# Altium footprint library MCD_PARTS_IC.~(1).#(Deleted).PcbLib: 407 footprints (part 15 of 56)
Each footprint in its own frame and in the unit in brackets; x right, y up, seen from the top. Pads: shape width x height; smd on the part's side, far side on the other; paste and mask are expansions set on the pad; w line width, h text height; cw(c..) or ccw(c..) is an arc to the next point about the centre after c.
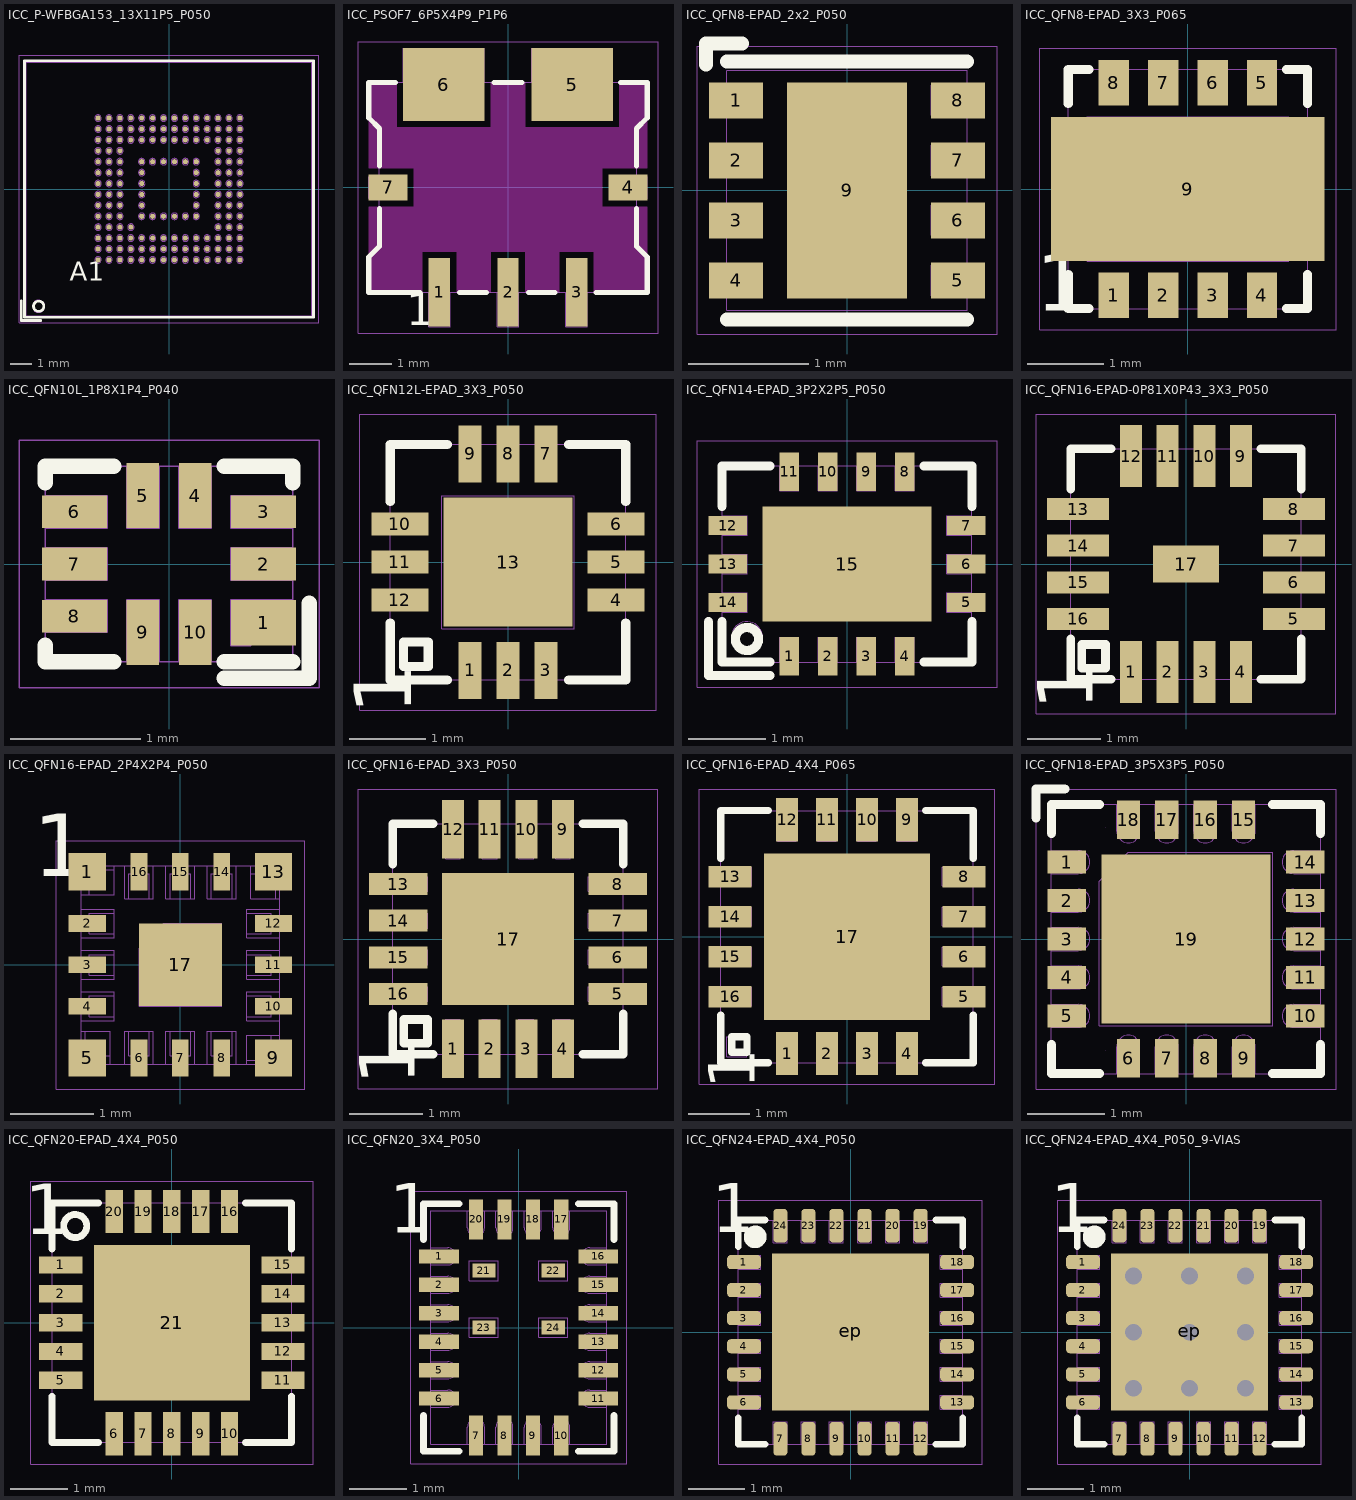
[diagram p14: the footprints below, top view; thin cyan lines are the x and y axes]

## ICC_P-WFBGA153_13X11P5_P050 [mm]
height 1
pads (153):
  round 0.23 smd mask+0.05: A1(-3.25,-3.25) A2(-3.25,-2.75) A3(-3.25,-2.25) A4(-3.25,-1.75) A5(-3.25,-1.25) A6(-3.25,-0.75) A7(-3.25,-0.25) A8(-3.25,0.25) A9(-3.25,0.75) A10(-3.25,1.25) A11(-3.25,1.75) A12(-3.25,2.25) A13(-3.25,2.75) A14(-3.25,3.25) B1(-2.75,-3.25) B2(-2.75,-2.75) B3(-2.75,-2.25) B4(-2.75,-1.75) B5(-2.75,-1.25) B6(-2.75,-0.75) B7(-2.75,-0.25) B8(-2.75,0.25) B9(-2.75,0.75) B10(-2.75,1.25) B11(-2.75,1.75) B12(-2.75,2.25) B13(-2.75,2.75) B14(-2.75,3.25) C1(-2.25,-3.25) C2(-2.25,-2.75) C3(-2.25,-2.25) C4(-2.25,-1.75) C5(-2.25,-1.25) C6(-2.25,-0.75) C7(-2.25,-0.25) C8(-2.25,0.25) C9(-2.25,0.75) C10(-2.25,1.25) C11(-2.25,1.75) C12(-2.25,2.25) C13(-2.25,2.75) C14(-2.25,3.25) D1(-1.75,-3.25) D2(-1.75,-2.75) D3(-1.75,-2.25) D4(-1.75,-1.75) D12(-1.75,2.25) D13(-1.75,2.75) D14(-1.75,3.25) E1(-1.25,-3.25) E2(-1.25,-2.75) E3(-1.25,-2.25) E5(-1.25,-1.25) E6(-1.25,-0.75) E7(-1.25,-0.25) E8(-1.25,0.25) E9(-1.25,0.75) E10(-1.25,1.25) E12(-1.25,2.25) E13(-1.25,2.75) E14(-1.25,3.25) F1(-0.75,-3.25) F2(-0.75,-2.75) F3(-0.75,-2.25) F5(-0.75,-1.25) F10(-0.75,1.25) F12(-0.75,2.25) F13(-0.75,2.75) F14(-0.75,3.25) G1(-0.25,-3.25) G2(-0.25,-2.75) G3(-0.25,-2.25) G5(-0.25,-1.25) G10(-0.25,1.25) G12(-0.25,2.25) G13(-0.25,2.75) G14(-0.25,3.25) H1(0.25,-3.25) H2(0.25,-2.75) H3(0.25,-2.25) H5(0.25,-1.25) H10(0.25,1.25) H12(0.25,2.25) H13(0.25,2.75) H14(0.25,3.25) J1(0.75,-3.25) J2(0.75,-2.75) J3(0.75,-2.25) J5(0.75,-1.25) J10(0.75,1.25) J12(0.75,2.25) J13(0.75,2.75) J14(0.75,3.25) K1(1.25,-3.25) K2(1.25,-2.75) K3(1.25,-2.25) K5(1.25,-1.25) K6(1.25,-0.75) K7(1.25,-0.25) K8(1.25,0.25) K9(1.25,0.75) K10(1.25,1.25) K12(1.25,2.25) K13(1.25,2.75) K14(1.25,3.25) L1(1.75,-3.25) L2(1.75,-2.75) L3(1.75,-2.25) L12(1.75,2.25) L13(1.75,2.75) L14(1.75,3.25) M1(2.25,-3.25) M2(2.25,-2.75) M3(2.25,-2.25) M4(2.25,-1.75) M5(2.25,-1.25) M6(2.25,-0.75) M7(2.25,-0.25) M8(2.25,0.25) M9(2.25,0.75) M10(2.25,1.25) M11(2.25,1.75) M12(2.25,2.25) M13(2.25,2.75) M14(2.25,3.25) N1(2.75,-3.25) N2(2.75,-2.75) N3(2.75,-2.25) N4(2.75,-1.75) N5(2.75,-1.25) N6(2.75,-0.75) N7(2.75,-0.25) N8(2.75,0.25) N9(2.75,0.75) N10(2.75,1.25) N11(2.75,1.75) N12(2.75,2.25) N13(2.75,2.75) N14(2.75,3.25) P1(3.25,-3.25) P2(3.25,-2.75) P3(3.25,-2.25) P4(3.25,-1.75) P5(3.25,-1.25) P6(3.25,-0.75) P7(3.25,-0.25) P8(3.25,0.25) P9(3.25,0.75) P10(3.25,1.25) P11(3.25,1.75) P12(3.25,2.25) P13(3.25,2.75) P14(3.25,3.25)
Top Overlay:
  circle w0.12: c-5.975,-5.375 r0.236
  lines w0.12: -6.775,-5.125 -6.775,-6.025 -5.875,-6.025 ; -6.625,-5.875 6.625,-5.875 6.625,5.875 -6.625,5.875 -6.625,-5.875
  text "A1" at -4.55,-4.5 h1.5
M14-Top Assembly:
  drawing of 158 lines, arcs and shapes, not listed
  text "A1" at -3.5,-3.4 h0.5
  text "'.Designator'" at -2,-0.5 h0.75
M16-Top Courtyard:
  lines w0.01: -6.875,-6.125 6.875,-6.125 6.875,6.125 -6.875,6.125 -6.875,-6.125
3D body "WFBGA-153.STEP": height 0.78, standoff -0.02, extent -6.5,-5.75 6.5,5.75
3D body: height 1, standoff 0, extent -6.555,-5.805 6.555,5.805

## ICC_PSOF7_6P5X4P9_P1P6 [mm] "MCD-04242"
height 1.6
pads (7):
  rect 0.5x1.6 smd mask+0.05: 1(-1.6,-2.45) 2(0,-2.45) 3(1.6,-2.45)
  rect 0.9x0.6 smd mask+0.05: 4(2.8,0) 7(-2.8,0)
  rect 1.9x1.7 smd mask+0.05: 5(1.5,2.4) 6(-1.5,2.4)
Top Overlay:
  lines w0.12: -3,-0.5 -3,-1.375 -3.25,-1.625 -3.25,-2.45 -2.05,-2.45 ; -3,0.5 -3,1.375 -3.25,1.625 -3.25,2.45 -2.625,2.45 ; -1.125,-2.45 -0.5,-2.45 ; -0.325,2.45 0.325,2.45 ; 0.475,-2.45 1.1,-2.45 ; 2.05,-2.45 3.25,-2.45 3.25,-1.625 3,-1.375 3,-0.5 ; 2.625,2.45 3.25,2.45 3.25,1.625 3,1.375 3,0.5
  text "1" at -2.375,-3.475 h1.3
Keep-Out Layer:
  region: -0.4,2.45 0.4,2.45 0.4,1.4 2.6,1.4 2.6,2.45 3.25,2.45 3.25,0.45 2.2,0.45 2.2,-0.45 3.25,-0.45 3.25,-2.45 2,-2.45 2,-1.5 1.2,-1.5 1.2,-2.45 0.4,-2.45 0.4,-1.5 -0.4,-1.5 -0.4,-2.45 -1.2,-2.45 -1.2,-1.5 -2,-1.5 -2,-2.45 -3.25,-2.45 -3.25,-0.45 -2.2,-0.45 -2.2,0.45 -3.25,0.45 -3.25,2.45 -2.6,2.45 -2.6,1.4 -0.4,1.4
M14-Top Assembly:
  lines w0.01: -2.45,2.45 -2.45,3.25 -0.55,3.25 -0.55,2.45 ; -1.85,-2.45 -1.85,-3.25 -1.35,-3.25 -1.35,-2.45 ; -0.25,-2.45 -0.25,-3.25 0.25,-3.25 0.25,-2.45 ; 0.55,2.45 0.55,3.25 2.45,3.25 2.45,2.45 ; 1.35,-2.45 1.35,-3.25 1.85,-3.25 1.85,-2.45 ; -3,-0.25 -3,-1.375 -3.25,-1.625 -3.25,-2.45 3.25,-2.45 3.25,-1.625 3,-1.375 3,-0.25 ; -3,-0.25 -3.25,-0.25 -3.25,0.25 -3,0.25 ; -3,-0.25 -3,0.25 ; -3,0.25 -3,1.375 -3.25,1.625 -3.25,2.45 3.25,2.45 3.25,1.625 3,1.375 3,0.25 ; 3,-0.25 3.25,-0.25 3.25,0.25 3,0.25 ; 3,-0.25 3,0.25
  text "1" at -1.8,-3.25 h1.3
  text "'.Designator'" at -2,-0.5 h0.75
M16-Top Courtyard:
  lines w0.01: -3.5,-3.4 3.5,-3.4 3.5,3.4 -3.5,3.4 -3.5,-3.4
3D body: height 0.35, standoff 0, extent 1.35,-3.25 1.85,-2.45
3D body: height 0.35, standoff 0, extent -0.25,-3.25 0.25,-2.45
3D body: height 0.35, standoff 0, extent 3,-0.25 3.25,0.25
3D body: height 0.35, standoff 0, extent 0.55,2.45 2.45,3.25
3D body: height 0.35, standoff 0, extent -2.45,2.45 -0.55,3.25
3D body: height 0.35, standoff 0, extent -1.85,-3.25 -1.35,-2.45
3D body: height 0.35, standoff 0, extent -3.25,-0.25 -3,0.25
3D body: height 1.6, standoff 0, extent -3,-2.45 3,2.45

## ICC_QFN8-EPAD_2x2_P050 [mm] "MCD-03561"
height 1
pads (9):
  rect 0.45x0.3 smd mask+0.05: 1(-0.925,0.75) 2(-0.925,0.25) 3(-0.925,-0.25) 4(-0.925,-0.75) 5(0.925,-0.75) 6(0.925,-0.25) 7(0.925,0.25) 8(0.925,0.75)
  rect 1x1.8 smd mask+0.05: 9(0,0)
Top Overlay:
  lines w0.12: -1.175,1.05 -1.175,1.225 -0.875,1.225 ; -1,-1.075 1,-1.075 ; -1,1.075 1,1.075
M14-Top Assembly:
  lines w0.01: -1,-0.875 -0.7,-0.875 -0.7,-0.625 -1,-0.625 ; -1,-0.375 -0.7,-0.375 -0.7,-0.125 -1,-0.125 ; -1,0.125 -0.7,0.125 -0.7,0.375 -1,0.375 ; -1,0.625 -0.7,0.625 -0.7,0.875 -1,0.875 ; 1,-0.875 0.7,-0.875 0.7,-0.625 1,-0.625 ; 1,-0.375 0.7,-0.375 0.7,-0.125 1,-0.125 ; 1,0.125 0.7,0.125 0.7,0.375 1,0.375 ; 1,0.625 0.7,0.625 0.7,0.875 1,0.875 ; -1,-1 ccw(c-1,-1) -1,-1 1,-1 1,1 -1,1 ccw(c-1,1) -1,1 -1,-1 ; -0.45,-0.85 0.45,-0.85 0.45,0.85 -0.45,0.85 -0.45,-0.85
  text "'.Designator'" at -1.813,-0.17 h0.75
  text "1" at -0.891,0.638 h0.35
  text "4" at -0.927,-0.862 h0.35
  text "5" at 0.776,-0.858 h0.35
  text "8" at 0.776,0.64 h0.35
  text "9" at -0.073,-0.11 h0.35
M16-Top Courtyard:
  lines w0.01: -1.25,-1.2 1.25,-1.2 1.25,1.2 -1.25,1.2 -1.25,-1.2
3D body "QFN8.STEP": height 0.95, standoff 0, extent -1.05,-1 1.05,1

## ICC_QFN8-EPAD_3X3_P065 [mm]
height 1
pads (9):
  rect 0.4x0.6 smd paste+0 mask+0.05: 1(-0.975,-1.4) 2(-0.325,-1.4) 3(0.325,-1.4) 4(0.975,-1.4) 5(0.975,1.4) 6(0.325,1.4) 7(-0.325,1.4) 8(-0.975,1.4)
  rect 3.6x1.9 smd paste+0 mask+0: 9(0,0)
Top Overlay:
  lines w0.12: -1.575,-1.125 -1.575,-1.575 -1.3,-1.575 ; -1.575,1.125 -1.575,1.575 -1.3,1.575 ; 1.3,-1.575 1.575,-1.575 1.575,-1.125 ; 1.3,1.575 1.575,1.575 1.575,1.125
  text "1" at -2,-1.85 h1.3
M14-Top Assembly:
  lines w0.01: -1.15,-1.575 -1.15,-1.2 -0.8,-1.2 -0.8,-1.575 ; -1.15,1.575 -1.15,1.2 -0.8,1.2 -0.8,1.575 ; -0.5,-1.575 -0.5,-1.2 -0.15,-1.2 -0.15,-1.575 ; -0.5,1.575 -0.5,1.2 -0.15,1.2 -0.15,1.575 ; 0.15,-1.575 0.15,-1.2 0.5,-1.2 0.5,-1.575 ; 0.15,1.575 0.15,1.2 0.5,1.2 0.5,1.575 ; 0.8,-1.575 0.8,-1.2 1.15,-1.2 1.15,-1.575 ; 0.8,1.575 0.8,1.2 1.15,1.2 1.15,1.575 ; -1.575,-1.575 1.575,-1.575 1.575,1.575 -1.575,1.575 -1.575,-1.575 ; -1.575,-0.45 -1.525,-0.45 -1.325,-0.45 -1.325,-0.95 1.325,-0.95 1.325,-0.45 1.575,-0.45 1.575,-0.25 1.325,-0.25 1.325,0.25 1.575,0.25 1.575,0.45 1.325,0.45 1.325,0.95 -1.325,0.95 -1.325,0.45 -1.575,0.45 -1.575,0.25 -1.325,0.25 -1.325,-0.25 -1.575,-0.25 -1.575,-0.45
  text "1" at -1.075,-1.55 h0.7
  text "4" at 0.8,-1.55 h0.7
  text "5" at 0.825,1.1 h0.7
  text "8" at -1.125,1.1 h0.7
  text "'.Designator'" at -2,-0.5 h0.75
M16-Top Courtyard:
  lines w0.01: -1.95,-1.85 -1.95,1.85 1.95,1.85 1.95,-1.85 -1.95,-1.85
3D body: height 1, standoff 0, extent -1.58,-1.58 1.58,1.58
3D body "QFN8-EPAD-3X3-P065.STEP": height 0.9, standoff 0, extent -1.5,-1.501 1.5,1.501

## ICC_QFN10L_1P8X1P4_P040 [mm] "SOLDER MASK REGISTRATION 38UM"
height 0.55
pads (10):
  rect 0.5x0.35 smd mask+0.038: 1(0.725,-0.45)
  rect 0.5x0.25 smd mask+0.038: 2(0.725,0) 3(0.725,0.4) 6(-0.725,0.4) 7(-0.725,0) 8(-0.725,-0.4)
  rect 0.25x0.5 smd mask+0.038: 4(0.2,0.525) 5(-0.2,0.525) 9(-0.2,-0.525) 10(0.2,-0.525)
Top Overlay:
  lines w0.12: -0.95,-0.625 -0.95,-0.75 -0.425,-0.75 ; -0.95,0.625 -0.95,0.75 -0.425,0.75 ; 0.425,-0.875 1.075,-0.875 1.075,-0.3 ; 0.425,-0.75 0.95,-0.75 ; 0.425,0.75 0.95,0.75 0.95,0.625
M14-Top Assembly:
  lines w0.01: -0.95,-0.525 -0.475,-0.525 -0.475,-0.275 -0.95,-0.275 ; -0.95,-0.125 -0.475,-0.125 -0.475,0.125 -0.95,0.125 ; -0.95,0.275 -0.475,0.275 -0.475,0.525 -0.95,0.525 ; -0.325,-0.75 -0.325,-0.275 -0.075,-0.275 -0.075,-0.75 ; -0.325,0.75 -0.325,0.275 -0.075,0.275 -0.075,0.75 ; 0.075,-0.75 0.075,-0.275 0.325,-0.275 0.325,-0.75 ; 0.075,0.75 0.075,0.275 0.325,0.275 0.325,0.75 ; 0.95,-0.525 0.625,-0.525 0.625,-0.625 0.475,-0.625 0.475,-0.525 0.475,-0.275 0.95,-0.275 ; 0.95,-0.125 0.475,-0.125 0.475,0.125 0.95,0.125 ; 0.95,0.275 0.475,0.275 0.475,0.525 0.95,0.525 ; -0.95,-0.75 -0.95,0.75 0.95,0.75 0.95,-0.75 -0.95,-0.75
  text "10" at 0,-0.7 h0.5
  text "9" at -0.3,-0.7 h0.5
  text "8" at -0.9,-0.3 h0.5
  text "7" at -0.9,0.1 h0.5
  text "6" at -0.9,0.5 h0.5
  text "5" at -0.3,0.4 h0.5
  text "4" at 0.1,0.4 h0.5
  text "3" at 0.9,0.3 h0.5
  text "2" at 0.9,-0.1 h0.5
  text "1" at 0.9,-0.475 h0.5
  text "'.Designator'" at -2,-0.5 h0.75
M16-Top Courtyard:
  lines w0.01: -1.15,-0.95 -1.15,0.95 1.15,0.95 1.15,-0.95 -1.15,-0.95
3D body: height 0.55, standoff 0, extent -0.95,-0.75 0.95,0.75
3D body: height 0.56, standoff 0.55, extent 0.621,-0.68 0.88,-0.42

## ICC_QFN12L-EPAD_3X3_P050 [mm] "MCD-01809"
height 0.8
pads (13):
  rect 0.3x0.75 smd mask+0.05: 1(-0.5,-1.425) 2(0,-1.425) 3(0.5,-1.425) 7(0.5,1.425) 8(0,1.425) 9(-0.5,1.425)
  rect 0.75x0.3 smd mask+0.05: 4(1.425,-0.5) 5(1.425,0) 6(1.425,0.5) 10(-1.425,0.5) 11(-1.425,0) 12(-1.425,-0.5)
  rect 1.7x1.7 smd mask+0.05: 13(0,0)
Top Overlay:
  lines w0.12: -1.55,-0.8 -1.55,-1.55 -0.8,-1.55 ; -1.55,0.8 -1.55,1.55 -0.8,1.55 ; 0.8,-1.55 1.55,-1.55 1.55,-0.8 ; 0.8,1.55 1.55,1.55 1.55,0.8 ; -1.375,-1.375 -1.05,-1.375 -1.05,-1.05 -1.375,-1.05 -1.375,-1.375
  text "1" at -1.025,-2 h1.3
M14-Top Assembly:
  lines w0.01: -1.55,-0.6 -1.15,-0.6 -1.15,-0.4 -1.55,-0.4 ; -1.55,-0.1 -1.15,-0.1 -1.15,0.1 -1.55,0.1 ; -1.55,0.4 -1.15,0.4 -1.15,0.6 -1.55,0.6 ; -0.6,-1.55 -0.6,-1.15 -0.4,-1.15 -0.4,-1.55 ; -0.6,1.55 -0.6,1.15 -0.4,1.15 -0.4,1.55 ; -0.1,-1.55 -0.1,-1.15 0.1,-1.15 0.1,-1.55 ; -0.1,1.55 -0.1,1.15 0.1,1.15 0.1,1.55 ; 0.4,-1.55 0.4,-1.15 0.6,-1.15 0.6,-1.55 ; 0.4,1.55 0.4,1.15 0.6,1.15 0.6,1.55 ; 1.55,-0.6 1.15,-0.6 1.15,-0.4 1.55,-0.4 ; 1.55,-0.1 1.15,-0.1 1.15,0.1 1.55,0.1 ; 1.55,0.4 1.15,0.4 1.15,0.6 1.55,0.6 ; -1.55,-1.55 -1.55,1.55 1.55,1.55 1.55,-1.55 -1.55,-1.55 ; -1.375,-1.375 -1.05,-1.375 -1.05,-1.05 -1.375,-1.05 -1.375,-1.375 ; -0.875,-0.875 0.875,-0.875 0.875,0.875 -0.875,0.875 -0.875,-0.875
  text "'.Designator'" at -2,-0.5 h0.75
  text "13" at -0.15,-0.125 h0.4
  text "9" at -0.575,1.225 h0.4
  text "7" at 0.425,1.2 h0.4
  text "6" at 1.275,0.375 h0.4
  text "4" at 1.25,-0.65 h0.4
  text "3" at 0.425,-1.475 h0.4
  text "1" at -0.575,-1.475 h0.4
  text "10" at -1.525,0.4 h0.4
  text "12" at -1.5,-0.625 h0.4
M16-Top Courtyard:
  lines w0.01: -1.95,-1.95 -1.95,1.95 1.95,1.95 1.95,-1.95 -1.95,-1.95
3D body "User Library-QFN12_3x3x0_8.STEP": height 0.78, standoff -0.02, extent -1.51,-1.51 1.51,1.51
3D body: height 0.8, standoff 0, extent -1.55,-1.55 1.55,1.55

## ICC_QFN14-EPAD_3P2X2P5_P050 [mm] "MCD-02349"
height 0.9
pads (15):
  rect 0.25x0.5 smd mask+0.05: 1(-0.75,-1.2) 2(-0.25,-1.2) 3(0.25,-1.2) 4(0.75,-1.2) 8(0.75,1.2) 9(0.25,1.2) 10(-0.25,1.2) 11(-0.75,1.2)
  rect 0.5x0.25 smd mask+0.05: 5(1.55,-0.5) 6(1.55,0) 7(1.55,0.5) 12(-1.55,0.5) 13(-1.55,0) 14(-1.55,-0.5)
  rect 2.2x1.5 smd mask+0.05: 15(0,0)
Top Overlay:
  circle w0.12: c-1.3,-0.975 r0.15
  lines w0.12: -1.8,-0.75 -1.8,-1.45 -1,-1.45 ; -1.625,-0.75 -1.625,-1.275 -1,-1.275 ; -1.625,0.75 -1.625,1.275 -1,1.275 ; 1,-1.275 1.625,-1.275 1.625,-0.75 ; 1,1.275 1.625,1.275 1.625,0.75
M14-Top Assembly:
  circle w0.01: c-1.3,-0.95 r0.2
  lines w0.01: -1.625,-0.625 -1.3,-0.625 -1.3,-0.375 -1.625,-0.375 ; -1.625,-0.125 -1.3,-0.125 -1.3,0.125 -1.625,0.125 ; -1.625,0.375 -1.3,0.375 -1.3,0.625 -1.625,0.625 ; -0.875,-1.275 -0.875,-0.95 -0.625,-0.95 -0.625,-1.275 ; -0.875,1.275 -0.875,0.95 -0.625,0.95 -0.625,1.275 ; -0.375,-1.275 -0.375,-0.95 -0.125,-0.95 -0.125,-1.275 ; -0.375,1.275 -0.375,0.95 -0.125,0.95 -0.125,1.275 ; 0.125,-1.275 0.125,-0.95 0.375,-0.95 0.375,-1.275 ; 0.125,1.275 0.125,0.95 0.375,0.95 0.375,1.275 ; 0.625,-1.275 0.625,-0.95 0.875,-0.95 0.875,-1.275 ; 0.625,1.275 0.625,0.95 0.875,0.95 0.875,1.275 ; 1.625,-0.625 1.3,-0.625 1.3,-0.375 1.625,-0.375 ; 1.625,-0.125 1.3,-0.125 1.3,0.125 1.625,0.125 ; 1.625,0.375 1.3,0.375 1.3,0.625 1.625,0.625 ; -1.625,-1.275 -1.625,1.275 1.625,1.275 1.625,-1.275 -1.625,-1.275 ; -1.05,-0.45 -1.05,0.7 1.05,0.7 1.05,-0.7 -0.8,-0.7 -1.05,-0.45
  text "15" at -0.175,-0.125 h0.4
  text "14" at -1.6,-0.325 h0.4
  text "12" at -1.6,0.675 h0.4
  text "11" at -0.9,1 h0.4
  text "8" at 0.675,1 h0.4
  text "7" at 1.6,0.425 h0.4
  text "5" at 1.6,-0.575 h0.4
  text "4" at 0.65,-1.25 h0.4
  text "'.Designator'" at -2,-0.025 h0.75
  text "1" at -0.8,-1.25 h0.4
M16-Top Courtyard:
  lines w0.01: -1.95,-1.6 1.95,-1.6 1.95,1.6 -1.95,1.6 -1.95,-1.6
3D body: height 0.86, standoff 0.85, extent -1.499,-1.15 -1.101,-0.75
3D body: height 0.85, standoff 0.05, extent -1.625,-1.275 1.625,1.275
3D body: height 0.05, standoff 0, extent -1.625,0.375 -1.3,0.625
3D body: height 0.05, standoff 0, extent -1.625,-0.125 -1.3,0.125
3D body: height 0.05, standoff 0, extent -1.625,-0.625 -1.3,-0.375
3D body: height 0.05, standoff 0, extent -0.875,-1.275 -0.625,-0.95
3D body: height 0.05, standoff 0, extent -0.375,-1.275 -0.125,-0.95
3D body: height 0.05, standoff 0, extent 0.125,-1.275 0.375,-0.95
3D body: height 0.05, standoff 0, extent 0.625,-1.275 0.875,-0.95
3D body: height 0.05, standoff 0, extent 1.3,-0.625 1.625,-0.375
3D body: height 0.05, standoff 0, extent 1.3,-0.125 1.625,0.125
3D body: height 0.05, standoff 0, extent 1.3,0.375 1.625,0.625
3D body: height 0.05, standoff 0, extent 0.625,0.95 0.875,1.275
3D body: height 0.05, standoff 0, extent 0.125,0.95 0.375,1.275
3D body: height 0.05, standoff 0, extent -0.375,0.95 -0.125,1.275
3D body: height 0.05, standoff 0, extent -0.875,0.95 -0.625,1.275
3D body: height 0.05, standoff 0, extent -1.05,-0.7 1.05,0.7

## ICC_QFN16-EPAD-0P81X0P43_3X3_P050 [mm] "MCD-02527"
height 0.8
pads (17):
  rect 0.3x0.85 smd mask+0.05: 1(-0.75,-1.475) 2(-0.25,-1.475) 3(0.25,-1.475) 4(0.75,-1.475) 9(0.75,1.475) 10(0.25,1.475) 11(-0.25,1.475) 12(-0.75,1.475)
  rect 0.85x0.3 smd mask+0.05: 5(1.475,-0.75) 6(1.475,-0.25) 7(1.475,0.25) 8(1.475,0.75) 13(-1.475,0.75) 14(-1.475,0.25) 15(-1.475,-0.25) 16(-1.475,-0.75)
  rect 0.9x0.5 smd mask+0.05: 17(0,0)
Top Overlay:
  lines w0.12: -1.575,-1.025 -1.575,-1.575 -1.55,-1.575 -1.025,-1.575 ; -1.575,1.025 -1.575,1.575 -1.025,1.575 ; 1.025,-1.575 1.575,-1.575 1.575,-1.025 ; 1.025,1.575 1.575,1.575 1.575,1.025 ; -1.425,-1.425 -1.1,-1.425 -1.1,-1.1 -1.425,-1.1 -1.425,-1.425
  text "1" at -1.025,-2 h1.3
M14-Top Assembly:
  lines w0.01: -1.575,-0.85 -1.1,-0.85 -1.1,-0.65 -1.575,-0.65 ; -1.575,-0.35 -1.1,-0.35 -1.1,-0.15 -1.575,-0.15 ; -1.575,0.15 -1.1,0.15 -1.1,0.35 -1.575,0.35 ; -1.575,0.65 -1.1,0.65 -1.1,0.85 -1.575,0.85 ; -0.85,-1.575 -0.85,-1.1 -0.65,-1.1 -0.65,-1.575 ; -0.85,1.575 -0.85,1.1 -0.65,1.1 -0.65,1.575 ; -0.35,-1.575 -0.35,-1.1 -0.15,-1.1 -0.15,-1.575 ; -0.35,1.575 -0.35,1.1 -0.15,1.1 -0.15,1.575 ; 0.15,-1.575 0.15,-1.1 0.35,-1.1 0.35,-1.575 ; 0.15,1.575 0.15,1.1 0.35,1.1 0.35,1.575 ; 0.65,-1.575 0.65,-1.1 0.85,-1.1 0.85,-1.575 ; 0.65,1.575 0.65,1.1 0.85,1.1 0.85,1.575 ; 1.575,-0.85 1.1,-0.85 1.1,-0.65 1.575,-0.65 ; 1.575,-0.35 1.1,-0.35 1.1,-0.15 1.575,-0.15 ; 1.575,0.15 1.1,0.15 1.1,0.35 1.575,0.35 ; 1.575,0.65 1.1,0.65 1.1,0.85 1.575,0.85 ; -1.575,-1.575 -1.575,1.575 1.575,1.575 1.575,-1.575 -1.575,-1.575 ; -1.425,-1.425 -1.1,-1.425 -1.1,-1.1 -1.425,-1.1 -1.425,-1.425 ; -0.405,-0.215 0.405,-0.215 0.405,0.215 -0.405,0.215 -0.405,-0.215
  text "'.Designator'" at -2,-0.5 h0.75
  text "17" at -0.15,-0.125 h0.4
  text "16" at -1.507,-0.874 h0.4
  text "13" at -1.503,0.628 h0.4
  text "12" at -0.925,1.175 h0.4
  text "9" at 0.671,1.177 h0.4
  text "8" at 1.25,0.625 h0.4
  text "5" at 1.25,-0.875 h0.4
  text "4" at 0.66,-1.449 h0.4
  text "1" at -0.805,-1.449 h0.4
M16-Top Courtyard:
  lines w0.01: -2.05,-2.05 -2.05,2.05 2.05,2.05 2.05,-2.05 -2.05,-2.05
3D body: height 0.8, standoff 0, extent -1.575,-1.575 1.575,1.575
3D body "QFN16-EPAD_3X3_P050.STEP": height 0.9, standoff 0, extent -1.501,-1.501 1.501,1.501

## ICC_QFN16-EPAD_2P4X2P4_P050 [mm] "MCD-03832"
height 0.8
pads (17):
  rect 0.45x0.45 smd mask+0.05: 1(-1.125,1.125) 5(-1.125,-1.125) 9(1.125,-1.125) 13(1.125,1.125)
  rect 0.45x0.2 smd mask+0.05: 2(-1.125,0.5) 3(-1.125,0) 4(-1.125,-0.5) 10(1.125,-0.5) 11(1.125,0) 12(1.125,0.5)
  rect 0.2x0.45 smd mask+0.05: 6(-0.5,-1.125) 7(0,-1.125) 8(0.5,-1.125) 14(0.5,1.125) 15(0,1.125) 16(-0.5,1.125)
  rect 1x1 smd mask+0.05: 17(0,0)
Top Overlay:
  text "1" at -1.775,0.825 h1.3
M14-Top Assembly:
  lines w0.01: -1.15,-0.8 -1.15,-1.1 -0.85,-1.1 ; -1.1,0.85 -1.1,1.15 -0.8,1.15 ; -0.8,-0.625 -1.1,-0.625 -1.1,-0.375 -0.8,-0.375 ; -0.8,-0.125 -1.1,-0.125 -1.1,0.125 -0.8,0.125 ; -0.8,0.375 -1.1,0.375 -1.1,0.625 -0.8,0.625 ; -0.625,-0.8 -0.625,-1.1 -0.375,-1.1 -0.375,-0.8 ; -0.625,0.8 -0.625,1.1 -0.375,1.1 -0.375,0.8 ; -0.125,-0.8 -0.125,-1.1 0.125,-1.1 0.125,-0.8 ; -0.125,0.8 -0.125,1.1 0.125,1.1 0.125,0.8 ; 0.375,-0.8 0.375,-1.1 0.625,-1.1 0.625,-0.8 ; 0.375,0.8 0.375,1.1 0.625,1.1 0.625,0.8 ; 0.8,-1.15 1.1,-1.15 1.1,-0.85 ; 0.8,-0.625 1.1,-0.625 1.1,-0.375 0.8,-0.375 ; 0.8,-0.125 1.1,-0.125 1.1,0.125 0.8,0.125 ; 0.8,0.375 1.1,0.375 1.1,0.625 0.8,0.625 ; 0.85,1.1 1.15,1.1 1.15,0.8 ; -1.2,-1.2 1.2,-1.2 ; -1.2,-1.2 -1.2,1.2 ; -1.2,-1.2 -1.2,-0.8 -0.85,-0.8 -0.85,-1.2 -1.2,-1.2 ; -1.2,1.2 -1.2,0.85 -0.8,0.85 -0.8,1.2 -1.2,1.2 ; -1.2,1.2 1.2,1.2 ; 1.2,-1.2 1.2,-0.85 0.8,-0.85 0.8,-1.2 1.2,-1.2 ; 1.2,-1.2 1.2,1.2 ; 1.2,1.2 0.85,1.2 0.85,0.8 1.2,0.8 1.2,1.2 ; -1.2,-0.675 -0.8,-0.675 -0.8,-0.325 -1.2,-0.325 -1.2,-0.675 ; -1.2,-0.175 -0.8,-0.175 -0.8,0.175 -1.2,0.175 -1.2,-0.175 ; -1.2,0.325 -0.8,0.325 -0.8,0.675 -1.2,0.675 -1.2,0.325 ; -0.675,-1.2 -0.325,-1.2 -0.325,-0.8 -0.675,-0.8 -0.675,-1.2 ; -0.675,0.8 -0.675,1.2 -0.325,1.2 -0.325,0.8 -0.675,0.8 ; -0.5,-0.5 -0.5,0.2 -0.2,0.5 0.5,0.5 0.5,-0.5 -0.5,-0.5 ; -0.175,-1.2 0.175,-1.2 0.175,-0.8 -0.175,-0.8 -0.175,-1.2 ; -0.175,0.8 -0.175,1.2 0.175,1.2 0.175,0.8 -0.175,0.8 ; 0.325,-1.2 0.675,-1.2 0.675,-0.8 0.325,-0.8 0.325,-1.2 ; 0.325,0.8 0.325,1.2 0.675,1.2 0.675,0.8 0.325,0.8 ; 0.8,-0.675 0.8,-0.325 1.2,-0.325 1.2,-0.675 0.8,-0.675 ; 0.8,-0.175 0.8,0.175 1.2,0.175 1.2,-0.175 0.8,-0.175 ; 0.8,0.325 0.8,0.675 1.2,0.675 1.2,0.325 0.8,0.325
  text "'.Designator'" at -2,-0.5 h0.75
  text "17" at -0.15,-0.125 h0.4
  text "16" at -0.675,0.825 h0.4
  text "13" at 0.825,0.825 h0.4
  text "9" at 0.875,-1.125 h0.4
  text "5" at -1.075,-1.075 h0.4
  text "1" at -1.025,0.875 h0.4
M16-Top Courtyard:
  lines w0.01: -1.5,-1.5 -1.5,1.5 1.5,1.5 1.5,-1.5 -1.5,-1.5
3D body: height 0.81, standoff 0.8, extent -0.95,0.688 -0.65,0.988
3D body: height 0.8, standoff 0, extent -1.2,-1.2 1.2,1.2

## ICC_QFN16-EPAD_3X3_P050 [mm]
height 1
pads (17):
  rect 0.3x0.8 smd mask+0.05: 1(-0.75,-1.5) 2(-0.25,-1.5) 3(0.25,-1.5) 4(0.75,-1.5) 9(0.75,1.5) 10(0.25,1.5) 11(-0.25,1.5) 12(-0.75,1.5)
  rect 0.8x0.3 smd mask+0.05: 5(1.5,-0.75) 6(1.5,-0.25) 7(1.5,0.25) 8(1.5,0.75) 13(-1.5,0.75) 14(-1.5,0.25) 15(-1.5,-0.25) 16(-1.5,-0.75)
  rect 1.8x1.8 smd mask+0.05: 17(0,0)
Top Overlay:
  lines w0.12: -1.575,-1.025 -1.575,-1.575 -1.55,-1.575 -1.025,-1.575 ; -1.575,1.025 -1.575,1.575 -1.025,1.575 ; 1.025,-1.575 1.575,-1.575 1.575,-1.025 ; 1.025,1.575 1.575,1.575 1.575,1.025 ; -1.425,-1.425 -1.1,-1.425 -1.1,-1.1 -1.425,-1.1 -1.425,-1.425
  text "1" at -1.025,-2 h1.3
M14-Top Assembly:
  lines w0.01: -1.575,-0.85 -1.1,-0.85 -1.1,-0.65 -1.575,-0.65 ; -1.575,-0.35 -1.1,-0.35 -1.1,-0.15 -1.575,-0.15 ; -1.575,0.15 -1.1,0.15 -1.1,0.35 -1.575,0.35 ; -1.575,0.65 -1.1,0.65 -1.1,0.85 -1.575,0.85 ; -0.85,-1.575 -0.85,-1.1 -0.65,-1.1 -0.65,-1.575 ; -0.85,1.575 -0.85,1.1 -0.65,1.1 -0.65,1.575 ; -0.35,-1.575 -0.35,-1.1 -0.15,-1.1 -0.15,-1.575 ; -0.35,1.575 -0.35,1.1 -0.15,1.1 -0.15,1.575 ; 0.15,-1.575 0.15,-1.1 0.35,-1.1 0.35,-1.575 ; 0.15,1.575 0.15,1.1 0.35,1.1 0.35,1.575 ; 0.65,-1.575 0.65,-1.1 0.85,-1.1 0.85,-1.575 ; 0.65,1.575 0.65,1.1 0.85,1.1 0.85,1.575 ; 1.575,-0.85 1.1,-0.85 1.1,-0.65 1.575,-0.65 ; 1.575,-0.35 1.1,-0.35 1.1,-0.15 1.575,-0.15 ; 1.575,0.15 1.1,0.15 1.1,0.35 1.575,0.35 ; 1.575,0.65 1.1,0.65 1.1,0.85 1.575,0.85 ; -1.575,-1.575 -1.575,1.575 1.575,1.575 1.575,-1.575 -1.575,-1.575 ; -1.425,-1.425 -1.1,-1.425 -1.1,-1.1 -1.425,-1.1 -1.425,-1.425 ; -0.85,-0.85 0.85,-0.85 0.85,0.85 -0.85,0.85 -0.85,-0.85
  text "'.Designator'" at -2,0 h0.75
  text "17" at -0.15,-0.125 h0.4
  text "16" at -1.507,-0.874 h0.4
  text "13" at -1.503,0.628 h0.4
  text "12" at -0.925,1.175 h0.4
  text "9" at 0.671,1.177 h0.4
  text "8" at 1.25,0.625 h0.4
  text "5" at 1.25,-0.875 h0.4
  text "4" at 0.66,-1.449 h0.4
  text "1" at -0.805,-1.449 h0.4
M16-Top Courtyard:
  lines w0.01: -2.05,-2.05 -2.05,2.05 2.05,2.05 2.05,-2.05 -2.05,-2.05
3D body: height 1, standoff 0, extent -1.575,-1.575 1.575,1.575
3D body "QFN16-EPAD_3X3_P050.STEP": height 0.9, standoff 0, extent -1.501,-1.501 1.501,1.501

## ICC_QFN16-EPAD_4X4_P065 [mm]
height 1
pads (17):
  rect 0.35x0.7 smd mask+0.05: 1(-0.975,-1.9) 2(-0.325,-1.9) 3(0.325,-1.9) 4(0.975,-1.9) 9(0.975,1.9) 10(0.325,1.9) 11(-0.325,1.9) 12(-0.975,1.9)
  rect 0.7x0.35 smd mask+0.05: 5(1.9,-0.975) 6(1.9,-0.325) 7(1.9,0.325) 8(1.9,0.975) 13(-1.9,0.975) 14(-1.9,0.325) 15(-1.9,-0.325) 16(-1.9,-0.975)
  rect 2.7x2.7 smd mask+0.05: 17(0,0)
Top Overlay:
  lines w0.12: -2.05,-1.275 -2.05,-2.05 -1.275,-2.05 ; -2.05,1.275 -2.05,2.05 -1.275,2.05 ; 1.275,-2.05 2.05,-2.05 2.05,-1.275 ; 1.275,2.05 2.05,2.05 2.05,1.275 ; -1.875,-1.875 -1.875,-1.625 -1.625,-1.625 -1.625,-1.875 -1.875,-1.875
  text "1" at -1.25,-2.475 h1.3
M14-Top Assembly:
  lines w0.01: -2.05,-1.125 -1.55,-1.125 -1.55,-0.825 -2.05,-0.825 ; -2.05,-0.475 -1.55,-0.475 -1.55,-0.175 -2.05,-0.175 ; -2.05,0.175 -1.55,0.175 -1.55,0.475 -2.05,0.475 ; -2.05,0.825 -1.55,0.825 -1.55,1.125 -2.05,1.125 ; -1.125,-2.05 -1.125,-1.55 -0.825,-1.55 -0.825,-2.05 ; -1.125,2.05 -1.125,1.55 -0.825,1.55 -0.825,2.05 ; -0.475,-2.05 -0.475,-1.55 -0.175,-1.55 -0.175,-2.05 ; -0.475,2.05 -0.475,1.55 -0.175,1.55 -0.175,2.05 ; 0.175,-2.05 0.175,-1.55 0.475,-1.55 0.475,-2.05 ; 0.175,2.05 0.175,1.55 0.475,1.55 0.475,2.05 ; 0.825,-2.05 0.825,-1.55 1.125,-1.55 1.125,-2.05 ; 0.825,2.05 0.825,1.55 1.125,1.55 1.125,2.05 ; 2.05,-1.125 1.55,-1.125 1.55,-0.825 2.05,-0.825 ; 2.05,-0.475 1.55,-0.475 1.55,-0.175 2.05,-0.175 ; 2.05,0.175 1.55,0.175 1.55,0.475 2.05,0.475 ; 2.05,0.825 1.55,0.825 1.55,1.125 2.05,1.125 ; -2.05,-2.05 -2.05,2.05 2.05,2.05 2.05,-2.05 -2.05,-2.05 ; -1.95,-1.95 -1.625,-1.95 -1.625,-1.625 -1.95,-1.625 -1.95,-1.95
  text "16" at -1.975,-1.1 h0.4
  text "13" at -1.975,0.85 h0.4
  text "12" at -1.15,1.675 h0.4
  text "9" at 0.9,1.675 h0.4
  text "8" at 1.725,0.85 h0.4
  text "5" at 1.725,-1.1 h0.4
  text "4" at 0.875,-1.95 h0.4
  text "1" at -1.025,-1.95 h0.4
  text "'.Designator'" at -2,-0.5 h0.75
M16-Top Courtyard:
  lines w0.01: -2.4,-2.4 -2.4,2.4 2.4,2.4 2.4,-2.4 -2.4,-2.4
3D body "QFN16-EPAD_4X4_P065.STEP": height 0.85, standoff 0, extent -2.085,-2.085 2.085,2.085
3D body: height 1, standoff 0, extent -2.05,-2.05 2.05,2.05

## ICC_QFN18-EPAD_3P5X3P5_P050 [mm] "MCD-02600"
height 0.65
pads (19):
  rect 0.5x0.3 smd mask+0.05: 1(-1.55,1) 2(-1.55,0.5) 3(-1.55,0) 4(-1.55,-0.5) 5(-1.55,-1) 10(1.55,-1) 11(1.55,-0.5) 12(1.55,0) 13(1.55,0.5) 14(1.55,1)
  rect 0.3x0.5 smd mask+0.05: 6(-0.75,-1.55) 7(-0.25,-1.55) 8(0.25,-1.55) 9(0.75,-1.55) 15(0.75,1.55) 16(0.25,1.55) 17(-0.25,1.55) 18(-0.75,1.55)
  rect 2.2x2.2 smd mask+0.05: 19(0,0)
Top Overlay:
  lines w0.12: -1.95,1.575 -1.95,1.95 -1.575,1.95 ; -1.75,-1.375 -1.75,-1.75 -1.125,-1.75 ; -1.75,1.375 -1.75,1.75 -1.125,1.75 ; 1.125,-1.75 1.75,-1.75 1.75,-1.375 ; 1.125,1.75 1.75,1.75 1.75,1.375
M14-Top Assembly:
  lines w0.01: -1.75,-1.15 -1.4,-1.15 ccw(c-1.4,-1) -1.25,-1 ccw(c-1.4,-1) -1.4,-0.85 -1.75,-0.85 ; -1.75,-0.65 -1.4,-0.65 ccw(c-1.4,-0.5) -1.25,-0.5 ccw(c-1.4,-0.5) -1.4,-0.35 -1.75,-0.35 ; -1.75,-0.15 -1.4,-0.15 ccw(c-1.4,0) -1.25,0 ccw(c-1.4,0) -1.4,0.15 -1.75,0.15 ; -1.75,0.35 -1.4,0.35 ccw(c-1.4,0.5) -1.25,0.5 ccw(c-1.4,0.5) -1.4,0.65 -1.75,0.65 ; -1.75,0.85 -1.4,0.85 ccw(c-1.4,1) -1.25,1 ccw(c-1.4,1) -1.4,1.15 -1.75,1.15 ; -0.9,-1.75 -0.9,-1.4 cw(c-0.75,-1.4) -0.75,-1.25 cw(c-0.75,-1.4) -0.6,-1.4 -0.6,-1.75 ; -0.9,1.75 -0.9,1.4 ccw(c-0.75,1.4) -0.75,1.25 ccw(c-0.75,1.4) -0.6,1.4 -0.6,1.75 ; -0.4,-1.75 -0.4,-1.4 cw(c-0.25,-1.4) -0.25,-1.25 cw(c-0.25,-1.4) -0.1,-1.4 -0.1,-1.75 ; -0.4,1.75 -0.4,1.4 ccw(c-0.25,1.4) -0.25,1.25 ccw(c-0.25,1.4) -0.1,1.4 -0.1,1.75 ; 0.1,-1.75 0.1,-1.4 cw(c0.25,-1.4) 0.25,-1.25 cw(c0.25,-1.4) 0.4,-1.4 0.4,-1.75 ; 0.1,1.75 0.1,1.4 ccw(c0.25,1.4) 0.25,1.25 ccw(c0.25,1.4) 0.4,1.4 0.4,1.75 ; 0.6,-1.75 0.6,-1.4 cw(c0.75,-1.4) 0.75,-1.25 cw(c0.75,-1.4) 0.9,-1.4 0.9,-1.75 ; 0.6,1.75 0.6,1.4 ccw(c0.75,1.4) 0.75,1.25 ccw(c0.75,1.4) 0.9,1.4 0.9,1.75 ; 1.75,-1.15 1.4,-1.15 cw(c1.4,-1) 1.25,-1 cw(c1.4,-1) 1.4,-0.85 1.75,-0.85 ; 1.75,-0.65 1.4,-0.65 cw(c1.4,-0.5) 1.25,-0.5 cw(c1.4,-0.5) 1.4,-0.35 1.75,-0.35 ; 1.75,-0.15 1.4,-0.15 cw(c1.4,0) 1.25,0 cw(c1.4,0) 1.4,0.15 1.75,0.15 ; 1.75,0.35 1.4,0.35 cw(c1.4,0.5) 1.25,0.5 cw(c1.4,0.5) 1.4,0.65 1.75,0.65 ; 1.75,0.85 1.4,0.85 cw(c1.4,1) 1.25,1 cw(c1.4,1) 1.4,1.15 1.75,1.15 ; -1.05,1.45 -1.05,1.45 ; -1.05,1.45 -1.05,1.45 ; -1.75,-1.75 -1.75,1.75 1.75,1.75 1.75,-1.75 -1.75,-1.75 ; -1.125,-1.125 1.125,-1.125 1.125,1.125 -0.75,1.125 -1.125,0.75 -1.125,-1.125 ; -1.05,-1.45 -1.05,-1.45
  text "'.Designator'" at -2,-0.5 h0.75
  text "1" at -1.569,0.875 h0.4
  text "5" at -1.619,-1.121 h0.4
  text "10" at 1.325,-1.125 h0.4
  text "14" at 1.35,0.875 h0.4
  text "6" at -0.85,-1.65 h0.4
  text "9" at 0.675,-1.625 h0.4
  text "18" at -0.925,1.4 h0.4
  text "15" at 0.575,1.425 h0.4
  text "19" at -0.15,-0.125 h0.4
M16-Top Courtyard:
  lines w0.01: -1.95,-1.95 -1.95,1.95 1.95,1.95 1.95,-1.95 -1.95,-1.95
3D body "User Library-PQFN50P350X350X60_HS-19N.STEP": height 0.6, standoff 0, extent -1.75,-1.75 1.75,1.75

## ICC_QFN20-EPAD_4X4_P050 [mm] "MCD-02130"
height 1
pads (21):
  rect 0.75x0.3 smd mask+0.05: 1(-1.925,1) 2(-1.925,0.5) 3(-1.925,0) 4(-1.925,-0.5) 5(-1.925,-1) 11(1.925,-1) 12(1.925,-0.5) 13(1.925,0) 14(1.925,0.5) 15(1.925,1)
  rect 0.3x0.75 smd mask+0.05: 6(-1,-1.925) 7(-0.5,-1.925) 8(0,-1.925) 9(0.5,-1.925) 10(1,-1.925) 16(1,1.925) 17(0.5,1.925) 18(0,1.925) 19(-0.5,1.925) 20(-1,1.925)
  rect 2.7x2.7 smd mask+0.05: 21(0,0)
Top Overlay:
  circle w0.12: c-1.675,1.675 r0.2
  lines w0.12: -2.075,-1.275 -2.075,-2.075 -1.275,-2.075 ; -2.075,1.275 -2.075,2.075 -1.275,2.075 ; 1.275,-2.075 2.075,-2.075 2.075,-1.275 ; 1.275,2.075 2.075,2.075 2.075,1.275
  text "1" at -2.55,1.25 h1.5
M14-Top Assembly:
  circle w0.01: c-1.675,1.675 r0.2
  lines w0.01: -2.075,-1.125 -2.125,-1.125 -2.125,-0.875 -2.075,-0.875 ; -2.075,-0.625 -2.125,-0.625 -2.125,-0.375 -2.075,-0.375 ; -2.075,-0.125 -2.125,-0.125 -2.125,0.125 -2.075,0.125 ; -2.075,0.375 -2.125,0.375 -2.125,0.625 -2.075,0.625 ; -2.075,0.875 -2.125,0.875 -2.125,1.125 -2.075,1.125 ; -1.125,-2.075 -1.125,-2.125 -0.875,-2.125 -0.875,-2.075 ; -1.125,2.075 -1.125,2.125 -0.875,2.125 -0.875,2.075 ; -0.625,-2.075 -0.625,-2.125 -0.375,-2.125 -0.375,-2.075 ; -0.625,2.075 -0.625,2.125 -0.375,2.125 -0.375,2.075 ; -0.125,-2.075 -0.125,-2.125 0.125,-2.125 0.125,-2.075 ; -0.125,2.075 -0.125,2.125 0.125,2.125 0.125,2.075 ; 0.375,-2.075 0.375,-2.125 0.625,-2.125 0.625,-2.075 ; 0.375,2.075 0.375,2.125 0.625,2.125 0.625,2.075 ; 0.875,-2.075 0.875,-2.125 1.125,-2.125 1.125,-2.075 ; 0.875,2.075 0.875,2.125 1.125,2.125 1.125,2.075 ; 2.075,-1.125 2.125,-1.125 2.125,-0.875 2.075,-0.875 ; 2.075,-0.625 2.125,-0.625 2.125,-0.375 2.075,-0.375 ; 2.075,-0.125 2.125,-0.125 2.125,0.125 2.075,0.125 ; 2.075,0.375 2.125,0.375 2.125,0.625 2.075,0.625 ; 2.075,0.875 2.125,0.875 2.125,1.125 2.075,1.125 ; -2.075,-2.075 2.075,-2.075 2.075,2.075 -2.075,2.075 -2.075,-2.075 ; -1.325,-1.325 -1.325,1.325 1.325,1.325 1.325,-1.325 -1.325,-1.325
  text "'.Designator'" at -2,0.225 h0.75
  text "1" at -1.975,0.85 h0.5
  text "5" at -1.975,-1.15 h0.5
  text "6" at -1.1,-1.975 h0.5
  text "10" at 0.775,-1.975 h0.5
  text "11" at 1.6,-1.15 h0.5
  text "15" at 1.55,0.85 h0.5
  text "16" at 0.775,1.65 h0.5
  text "20" at -1.225,1.65 h0.5
  text "21" at -0.2,-0.15 h0.5
M16-Top Courtyard:
  lines w0.01: -2.45,-2.45 -2.45,2.45 -1.4,2.45 -1.1,2.45 2.45,2.45 2.45,-2.45 -2.45,-2.45
3D body: height 0.25, standoff 0, extent -2.125,0.875 -2.075,1.125
3D body: height 0.05, standoff 0, extent -2.125,0.875 -1.575,1.125
3D body: height 0.25, standoff 0, extent -2.125,0.375 -2.075,0.625
3D body: height 0.05, standoff 0, extent -2.125,0.375 -1.575,0.625
3D body: height 0.25, standoff 0, extent -2.125,-0.125 -2.075,0.125
3D body: height 0.05, standoff 0, extent -2.125,-0.125 -1.575,0.125
3D body: height 0.25, standoff 0, extent -2.125,-0.625 -2.075,-0.375
3D body: height 0.05, standoff 0, extent -2.125,-0.625 -1.575,-0.375
3D body: height 0.25, standoff 0, extent -2.125,-1.125 -2.075,-0.875
3D body: height 0.05, standoff 0, extent -2.125,-1.125 -1.575,-0.875
3D body: height 0.25, standoff 0, extent -1.125,-2.125 -0.875,-2.075
3D body: height 0.05, standoff 0, extent -1.125,-2.125 -0.875,-1.575
3D body: height 0.25, standoff 0, extent -0.625,-2.125 -0.375,-2.075
3D body: height 0.05, standoff 0, extent -0.625,-2.125 -0.375,-1.575
3D body: height 0.25, standoff 0, extent -0.125,-2.125 0.125,-2.075
3D body: height 0.05, standoff 0, extent -0.125,-2.125 0.125,-1.575
3D body: height 0.25, standoff 0, extent 0.375,-2.125 0.625,-2.075
3D body: height 0.05, standoff 0, extent 0.375,-2.125 0.625,-1.575
3D body: height 0.25, standoff 0, extent 0.875,-2.125 1.125,-2.075
3D body: height 0.05, standoff 0, extent 0.875,-2.125 1.125,-1.575
3D body: height 0.25, standoff 0, extent 2.075,-1.125 2.125,-0.875
3D body: height 0.05, standoff 0, extent 1.575,-1.125 2.125,-0.875
3D body: height 0.25, standoff 0, extent 2.075,-0.625 2.125,-0.375
3D body: height 0.05, standoff 0, extent 1.575,-0.625 2.125,-0.375
3D body: height 0.25, standoff 0, extent 2.075,-0.125 2.125,0.125
3D body: height 0.05, standoff 0, extent 1.575,-0.125 2.125,0.125
3D body: height 0.25, standoff 0, extent 2.075,0.375 2.125,0.625
3D body: height 0.05, standoff 0, extent 1.575,0.375 2.125,0.625
3D body: height 0.25, standoff 0, extent 2.075,0.875 2.125,1.125
3D body: height 0.05, standoff 0, extent 1.575,0.875 2.125,1.125
3D body: height 0.25, standoff 0, extent 0.875,2.075 1.125,2.125
3D body: height 0.05, standoff 0, extent 0.875,1.575 1.125,2.125
3D body: height 0.25, standoff 0, extent 0.375,2.075 0.625,2.125
3D body: height 0.05, standoff 0, extent 0.375,1.575 0.625,2.125
3D body: height 0.25, standoff 0, extent -0.125,2.075 0.125,2.125
3D body: height 0.05, standoff 0, extent -0.125,1.575 0.125,2.125
3D body: height 0.25, standoff 0, extent -0.625,2.075 -0.375,2.125
3D body: height 0.05, standoff 0, extent -0.625,1.575 -0.375,2.125
3D body: height 1, standoff 0.05, extent -2.075,-2.075 2.075,2.075
3D body: height 0.05, standoff 0, extent -1.125,1.575 -0.875,2.125
3D body: height 1.01, standoff 1, extent -1.923,1.426 -1.425,1.925
3D body: height 0.25, standoff 0, extent -1.125,2.075 -0.875,2.125
3D body: height 0.05, standoff 0, extent -1.325,-1.325 1.325,1.325

## ICC_QFN20_3X4_P050 [mm]
height 0.8
pads (24):
  rect 0.7x0.25 smd mask+0.05: 1(-1.4,1.25) 2(-1.4,0.75) 3(-1.4,0.25) 4(-1.4,-0.25) 5(-1.4,-0.75) 6(-1.4,-1.25) 11(1.4,-1.25) 12(1.4,-0.75) 13(1.4,-0.25) 14(1.4,0.25) 15(1.4,0.75) 16(1.4,1.25)
  rect 0.25x0.7 smd mask+0.05: 7(-0.75,-1.9) 8(-0.25,-1.9) 9(0.25,-1.9) 10(0.75,-1.9) 17(0.75,1.9) 18(0.25,1.9) 19(-0.25,1.9) 20(-0.75,1.9)
  rect 0.41x0.25 smd mask+0.05: 21(-0.61,1) 22(0.61,1) 23(-0.61,0) 24(0.61,0)
Top Overlay:
  lines w0.12: -1.675,-1.55 -1.675,-2.175 -1.05,-2.175 ; -1.675,1.55 -1.675,2.175 -1.05,2.175 ; 1.05,-2.175 1.675,-2.175 1.675,-1.55 ; 1.05,2.175 1.675,2.175 1.675,1.55
  text "1" at -2.275,1.375 h1.5
M14-Top Assembly:
  lines w0.01: -1.55,-1.4 -1.25,-1.4 ccw(c-1.25,-1.25) -1.1,-1.25 ccw(c-1.25,-1.25) -1.25,-1.1 -1.55,-1.1 ; -1.55,-0.9 -1.25,-0.9 ccw(c-1.25,-0.75) -1.1,-0.75 ccw(c-1.25,-0.75) -1.25,-0.6 -1.55,-0.6 ; -1.55,-0.4 -1.25,-0.4 ccw(c-1.25,-0.25) -1.1,-0.25 ccw(c-1.25,-0.25) -1.25,-0.1 -1.55,-0.1 ; -1.55,0.1 -1.25,0.1 ccw(c-1.25,0.25) -1.1,0.25 ccw(c-1.25,0.25) -1.25,0.4 -1.55,0.4 ; -1.55,0.6 -1.25,0.6 ccw(c-1.25,0.75) -1.1,0.75 ccw(c-1.25,0.75) -1.25,0.9 -1.55,0.9 ; -1.55,1.1 -1.25,1.1 ccw(c-1.25,1.25) -1.1,1.25 ccw(c-1.25,1.25) -1.25,1.4 -1.55,1.4 ; -0.9,-2.05 -0.9,-1.75 cw(c-0.75,-1.75) -0.75,-1.6 cw(c-0.75,-1.75) -0.6,-1.75 -0.6,-2.05 ; -0.9,2.05 -0.9,1.75 ccw(c-0.75,1.75) -0.75,1.6 ccw(c-0.75,1.75) -0.6,1.75 -0.6,2.05 ; -0.4,-2.05 -0.4,-1.75 cw(c-0.25,-1.75) -0.25,-1.6 cw(c-0.25,-1.75) -0.1,-1.75 -0.1,-2.05 ; -0.4,2.05 -0.4,1.75 ccw(c-0.25,1.75) -0.25,1.6 ccw(c-0.25,1.75) -0.1,1.75 -0.1,2.05 ; 0.1,-2.05 0.1,-1.75 cw(c0.25,-1.75) 0.25,-1.6 cw(c0.25,-1.75) 0.4,-1.75 0.4,-2.05 ; 0.1,2.05 0.1,1.75 ccw(c0.25,1.75) 0.25,1.6 ccw(c0.25,1.75) 0.4,1.75 0.4,2.05 ; 0.6,-2.05 0.6,-1.75 cw(c0.75,-1.75) 0.75,-1.6 cw(c0.75,-1.75) 0.9,-1.75 0.9,-2.05 ; 0.6,2.05 0.6,1.75 ccw(c0.75,1.75) 0.75,1.6 ccw(c0.75,1.75) 0.9,1.75 0.9,2.05 ; 1.55,-1.4 1.25,-1.4 cw(c1.25,-1.25) 1.1,-1.25 cw(c1.25,-1.25) 1.25,-1.1 1.55,-1.1 ; 1.55,-0.9 1.25,-0.9 cw(c1.25,-0.75) 1.1,-0.75 cw(c1.25,-0.75) 1.25,-0.6 1.55,-0.6 ; 1.55,-0.4 1.25,-0.4 cw(c1.25,-0.25) 1.1,-0.25 cw(c1.25,-0.25) 1.25,-0.1 1.55,-0.1 ; 1.55,0.1 1.25,0.1 cw(c1.25,0.25) 1.1,0.25 cw(c1.25,0.25) 1.25,0.4 1.55,0.4 ; 1.55,0.6 1.25,0.6 cw(c1.25,0.75) 1.1,0.75 cw(c1.25,0.75) 1.25,0.9 1.55,0.9 ; 1.55,1.1 1.25,1.1 cw(c1.25,1.25) 1.1,1.25 cw(c1.25,1.25) 1.25,1.4 1.55,1.4 ; -1.55,-2.05 1.55,-2.05 1.55,2.05 -1.55,2.05 -1.55,-2.05 ; -0.865,-0.175 -0.865,0.175 -0.355,0.175 -0.355,-0.175 -0.865,-0.175 ; -0.865,0.825 -0.355,0.825 -0.355,1.175 -0.865,1.175 -0.865,0.825 ; 0.355,-0.175 0.355,0.175 0.865,0.175 0.865,-0.175 0.355,-0.175 ; 0.355,0.825 0.865,0.825 0.865,1.175 0.355,1.175 0.355,0.825
  text "24" at 0.4,-0.16 h0.5
  text "23" at -0.82,-0.16 h0.5
  text "22" at 0.4,0.84 h0.5
  text "'.Designator'" at -2,-0.5 h0.75
  text "1" at -1.45,1.1 h0.5
  text "6" at -1.45,-1.4 h0.5
  text "7" at -0.85,-2 h0.5
  text "10" at 0.525,-2 h0.5
  text "11" at 1.15,-1.4 h0.5
  text "16" at 1.1,1.1 h0.5
  text "17" at 0.525,1.675 h0.5
  text "20" at -0.975,1.675 h0.5
  text "21" at -0.82,0.84 h0.5
M16-Top Courtyard:
  lines w0.01: -1.9,-2.4 -1.9,2.4 1.9,2.4 1.9,-2.4 -1.9,-2.4
3D body: height 0.81, standoff 0.8, extent -1.426,1.425 -0.926,1.925
3D body: height 0.8, standoff 0, extent -1.55,-2.05 1.55,2.05

## ICC_QFN24-EPAD_4X4_P050 [mm]
height 1
pads (25):
  rrect50% 0.6x0.25 smd mask+0.05: 1(-1.9,1.25) 2(-1.9,0.75) 3(-1.9,0.25) 4(-1.9,-0.25) 5(-1.9,-0.75) 6(-1.9,-1.25) 13(1.9,-1.25) 14(1.9,-0.75) 15(1.9,-0.25) 16(1.9,0.25) 17(1.9,0.75) 18(1.9,1.25)
  rrect50% 0.25x0.6 smd mask+0.05: 7(-1.25,-1.9) 8(-0.75,-1.9) 9(-0.25,-1.9) 10(0.25,-1.9) 11(0.75,-1.9) 12(1.25,-1.9) 19(1.25,1.9) 20(0.75,1.9) 21(0.25,1.9) 22(-0.25,1.9) 23(-0.75,1.9) 24(-1.25,1.9)
  rect 2.8x2.8 smd paste-10 mask+0.05: ep(0,0)
Top Overlay:
  circle w0.254: c-1.7,1.7 r0.075
  lines w0.12: -2,-1.525 -2,-2 -1.525,-2 ; -2,1.525 -2,2 -1.525,2 ; 1.525,-2 2,-2 2,-1.525 ; 1.525,2 2,2 2,1.525
  text "1" at -2.475,1.5 h1.5
Top Paste:
  rectangle: -0.875,-0.875 -0.125,-0.125
  rectangle: 0.125,-0.875 0.875,-0.125
  rectangle: 0.125,0.125 0.875,0.875
  rectangle: -0.875,0.125 -0.125,0.875
M14-Top Assembly:
  lines w0.01: -2,-1.375 -1.6,-1.375 -1.6,-1.125 -2,-1.125 ; -2,-0.875 -1.6,-0.875 -1.6,-0.625 -2,-0.625 ; -2,-0.375 -1.6,-0.375 -1.6,-0.125 -2,-0.125 ; -2,0.125 -1.6,0.125 -1.6,0.375 -2,0.375 ; -2,0.625 -1.6,0.625 -1.6,0.875 -2,0.875 ; -2,1.125 -1.6,1.125 -1.6,1.375 -2,1.375 ; -1.375,-2 -1.375,-1.6 -1.125,-1.6 -1.125,-2 ; -1.375,2 -1.375,1.6 -1.125,1.6 -1.125,2 ; -0.875,-2 -0.875,-1.6 -0.625,-1.6 -0.625,-2 ; -0.875,2 -0.875,1.6 -0.625,1.6 -0.625,2 ; -0.375,-2 -0.375,-1.6 -0.125,-1.6 -0.125,-2 ; -0.375,2 -0.375,1.6 -0.125,1.6 -0.125,2 ; 0.125,-2 0.125,-1.6 0.375,-1.6 0.375,-2 ; 0.125,2 0.125,1.6 0.375,1.6 0.375,2 ; 0.625,-2 0.625,-1.6 0.875,-1.6 0.875,-2 ; 0.625,2 0.625,1.6 0.875,1.6 0.875,2 ; 1.125,-2 1.125,-1.6 1.375,-1.6 1.375,-2 ; 1.125,2 1.125,1.6 1.375,1.6 1.375,2 ; 2,-1.375 1.6,-1.375 1.6,-1.125 2,-1.125 ; 2,-0.875 1.6,-0.875 1.6,-0.625 2,-0.625 ; 2,-0.375 1.6,-0.375 1.6,-0.125 2,-0.125 ; 2,0.125 1.6,0.125 1.6,0.375 2,0.375 ; 2,0.625 1.6,0.625 1.6,0.875 2,0.875 ; 2,1.125 1.6,1.125 1.6,1.375 2,1.375 ; -2,-2 -2,2 2,2 2,-2 -2,-2 ; -1.25,-1.25 1.25,-1.25 1.25,1.25 -1.25,1.25 -1.25,-1.25
  text "'.Designator'" at -2,0 h0.75
  text "6" at -2.35,-1.15 h0.5
  text "24" at -1.525,2.025 h0.5
  text "19" at 1.025,2.025 h0.5
  text "18" at 2.35,1.025 h0.5
  text "13" at 2.35,-1.475 h0.5
  text "12" at 1.025,-2.35 h0.5
  text "7" at -1.35,-2.35 h0.5
  text "1" at -2.35,1.325 h0.5
  text "ep" at -0.3,-0.225 h0.65
M16-Top Courtyard:
  lines w0.01: -2.35,-2.35 2.35,-2.35 2.35,2.35 -2.35,2.35 -2.35,-2.35
3D body "VQFN24-EPAD.STEP": height 1.05, standoff -0.03, extent -2.05,-2.05 2.05,2.05
3D body: height 1.1, standoff 1, extent -1.448,1.051 -1.05,1.45
3D body: height 1, standoff 0, extent -2,-2 2,2

## ICC_QFN24-EPAD_4X4_P050_9-VIAS [mm]
height 1
pads (25):
  rrect50% 0.6x0.25 smd mask+0.05: 1(-1.9,1.25) 2(-1.9,0.75) 3(-1.9,0.25) 4(-1.9,-0.25) 5(-1.9,-0.75) 6(-1.9,-1.25) 13(1.9,-1.25) 14(1.9,-0.75) 15(1.9,-0.25) 16(1.9,0.25) 17(1.9,0.75) 18(1.9,1.25)
  rrect50% 0.25x0.6 smd mask+0.05: 7(-1.25,-1.9) 8(-0.75,-1.9) 9(-0.25,-1.9) 10(0.25,-1.9) 11(0.75,-1.9) 12(1.25,-1.9) 19(1.25,1.9) 20(0.75,1.9) 21(0.25,1.9) 22(-0.25,1.9) 23(-0.75,1.9) 24(-1.25,1.9)
  rect 2.8x2.8 smd paste-10 mask+0.05: ep(0,0)
via -1,-1 diameter 0.6 hole 0.3
via 0,-1 diameter 0.6 hole 0.3
via 1,-1 diameter 0.6 hole 0.3
via 1,0 diameter 0.6 hole 0.3
via 1,1 diameter 0.6 hole 0.3
via 0,1 diameter 0.6 hole 0.3
via -1,1 diameter 0.6 hole 0.3
via -1,0 diameter 0.6 hole 0.3
via 0,0 diameter 0.6 hole 0.3
Top Overlay:
  circle w0.254: c-1.7,1.7 r0.075
  lines w0.12: -2,-1.525 -2,-2 -1.525,-2 ; -2,1.525 -2,2 -1.525,2 ; 1.525,-2 2,-2 2,-1.525 ; 1.525,2 2,2 2,1.525
  text "1" at -2.475,1.5 h1.5
Top Paste:
  rectangle: -0.875,0.125 -0.125,0.875
  rectangle: 0.125,0.125 0.875,0.875
  rectangle: 0.125,-0.875 0.875,-0.125
  rectangle: -0.875,-0.875 -0.125,-0.125
M14-Top Assembly:
  lines w0.01: -2,-1.375 -1.6,-1.375 -1.6,-1.125 -2,-1.125 ; -2,-0.875 -1.6,-0.875 -1.6,-0.625 -2,-0.625 ; -2,-0.375 -1.6,-0.375 -1.6,-0.125 -2,-0.125 ; -2,0.125 -1.6,0.125 -1.6,0.375 -2,0.375 ; -2,0.625 -1.6,0.625 -1.6,0.875 -2,0.875 ; -2,1.125 -1.6,1.125 -1.6,1.375 -2,1.375 ; -1.375,-2 -1.375,-1.6 -1.125,-1.6 -1.125,-2 ; -1.375,2 -1.375,1.6 -1.125,1.6 -1.125,2 ; -0.875,-2 -0.875,-1.6 -0.625,-1.6 -0.625,-2 ; -0.875,2 -0.875,1.6 -0.625,1.6 -0.625,2 ; -0.375,-2 -0.375,-1.6 -0.125,-1.6 -0.125,-2 ; -0.375,2 -0.375,1.6 -0.125,1.6 -0.125,2 ; 0.125,-2 0.125,-1.6 0.375,-1.6 0.375,-2 ; 0.125,2 0.125,1.6 0.375,1.6 0.375,2 ; 0.625,-2 0.625,-1.6 0.875,-1.6 0.875,-2 ; 0.625,2 0.625,1.6 0.875,1.6 0.875,2 ; 1.125,-2 1.125,-1.6 1.375,-1.6 1.375,-2 ; 1.125,2 1.125,1.6 1.375,1.6 1.375,2 ; 2,-1.375 1.6,-1.375 1.6,-1.125 2,-1.125 ; 2,-0.875 1.6,-0.875 1.6,-0.625 2,-0.625 ; 2,-0.375 1.6,-0.375 1.6,-0.125 2,-0.125 ; 2,0.125 1.6,0.125 1.6,0.375 2,0.375 ; 2,0.625 1.6,0.625 1.6,0.875 2,0.875 ; 2,1.125 1.6,1.125 1.6,1.375 2,1.375 ; -2,-2 2,-2 2,2 -2,2 -2,-2 ; -1.25,-1.25 -1.25,1.25 1.25,1.25 1.25,-1.25 -1.25,-1.25
  text "'.Designator'" at -2,0 h0.75
  text "ep" at -0.3,-0.225 h0.65
  text "1" at -2.35,1.325 h0.5
  text "7" at -1.35,-2.35 h0.5
  text "12" at 1.025,-2.35 h0.5
  text "13" at 2.35,-1.475 h0.5
  text "18" at 2.35,1.025 h0.5
  text "19" at 1.025,2.025 h0.5
  text "24" at -1.525,2.025 h0.5
  text "6" at -2.35,-1.15 h0.5
M16-Top Courtyard:
  lines w0.01: -2.35,-2.35 -2.35,2.35 2.35,2.35 2.35,-2.35 -2.35,-2.35
3D body: height 1, standoff 0, extent -2,-2 2,2
3D body: height 1.1, standoff 1, extent -1.448,1.051 -1.05,1.45
3D body "VQFN24-EPAD.STEP": height 1.05, standoff -0.03, extent -2.05,-2.05 2.05,2.05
